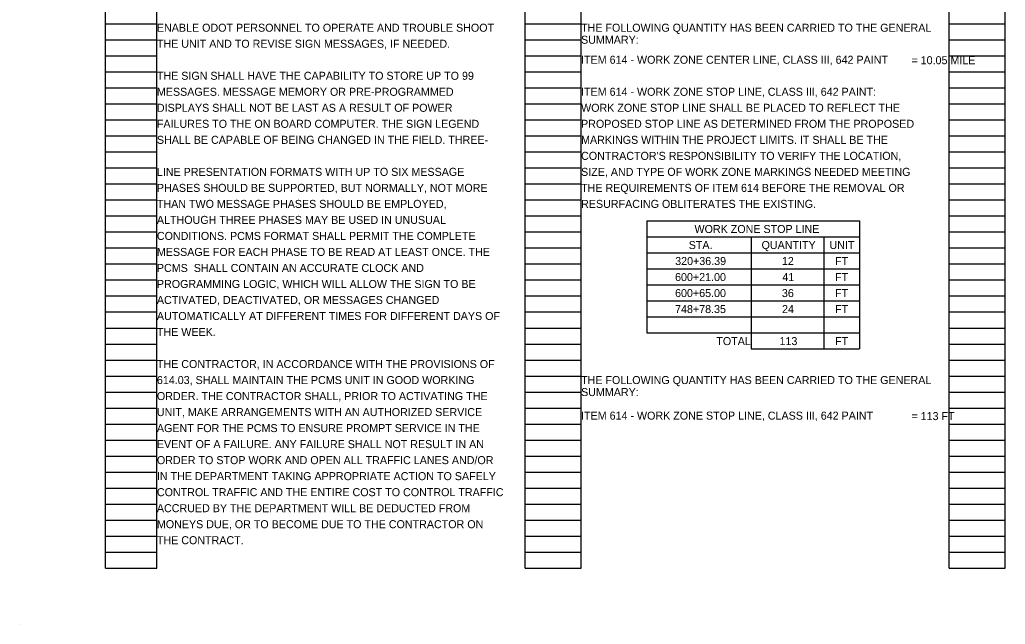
# Model space of a CAD drawing. Extents: x 63 to 145.9, y -75 to 21.1.
# Drawn here: x 62.97 to 80.21, y -50 to -39.43 of the extents above; entities that cross this region are included whole.
import ezdxf

# ---------------------------------------------------------------- set-up
doc = ezdxf.new("R2010")
doc.units = 0
doc.layers.add('AP_P_Airside', color=7, linetype='Continuous')
doc.layers.add('SH_Text', color=7, linetype='Continuous')

msp = doc.modelspace()

# ---------------------------------------------------------------- linework, layer by layer
at = {"layer": 'AP_P_Airside'}
for p, q in [((73.935, -42.945), (77.658, -42.945)), ((73.935, -42.945), (73.935, -44.905)), ((77.658, -42.945), (77.658, -45.185)), ((73.935, -43.225), (77.658, -43.225)), ((75.764, -43.225), (75.764, -45.185)), ((77.032, -43.225), (77.032, -45.185)), ((73.935, -43.505), (77.658, -43.505)), ((73.935, -43.785), (77.658, -43.785)), ((73.935, -44.065), (77.658, -44.065)), ((73.935, -44.345), (77.658, -44.345)), ((73.935, -44.625), (77.658, -44.625)), ((73.935, -44.905), (77.658, -44.905)), ((75.764, -45.185), (77.658, -45.185))]:
    msp.add_line(p, q, dxfattribs=at)
at = {"layer": 'SH_Text'}
for p, q in [((64.466, -49.02), (64.466, -28.86)), ((65.366, -49.02), (65.366, -28.86)), ((71.806, -49.02), (71.806, -28.86)), ((72.786, -49.02), (72.786, -28.86)), ((79.226, -49.02), (79.226, -28.86)), ((80.206, -49.02), (80.206, -28.86)), ((64.466, -39.5), (65.366, -39.5)), ((71.806, -39.5), (72.786, -39.5)), ((79.226, -39.5), (80.206, -39.5)), ((64.466, -39.78), (65.366, -39.78)), ((71.806, -39.78), (72.786, -39.78)), ((79.226, -39.78), (80.206, -39.78)), ((64.466, -40.06), (65.366, -40.06)), ((71.806, -40.06), (72.786, -40.06)), ((79.226, -40.06), (80.206, -40.06)), ((64.466, -40.34), (65.366, -40.34)), ((71.806, -40.34), (72.786, -40.34)), ((79.226, -40.34), (80.206, -40.34)), ((64.466, -40.62), (65.366, -40.62)), ((71.806, -40.62), (72.786, -40.62)), ((79.226, -40.62), (80.206, -40.62)), ((64.466, -40.9), (65.366, -40.9)), ((71.806, -40.9), (72.786, -40.9)), ((79.226, -40.9), (80.206, -40.9)), ((64.466, -41.18), (65.366, -41.18)), ((71.806, -41.18), (72.786, -41.18)), ((79.226, -41.18), (80.206, -41.18)), ((64.466, -41.46), (65.366, -41.46)), ((71.806, -41.46), (72.786, -41.46)), ((79.226, -41.46), (80.206, -41.46)), ((64.466, -41.74), (65.366, -41.74)), ((71.806, -41.74), (72.786, -41.74)), ((79.226, -41.74), (80.206, -41.74)), ((64.466, -42.02), (65.366, -42.02)), ((71.806, -42.02), (72.786, -42.02)), ((79.226, -42.02), (80.206, -42.02)), ((64.466, -42.3), (65.366, -42.3)), ((71.806, -42.3), (72.786, -42.3)), ((79.226, -42.3), (80.206, -42.3)), ((64.466, -42.58), (65.366, -42.58)), ((71.806, -42.58), (72.786, -42.58)), ((79.226, -42.58), (80.206, -42.58)), ((64.466, -42.86), (65.366, -42.86)), ((71.806, -42.86), (72.786, -42.86)), ((79.226, -42.86), (80.206, -42.86)), ((64.466, -43.14), (65.366, -43.14)), ((71.806, -43.14), (72.786, -43.14)), ((79.226, -43.14), (80.206, -43.14)), ((64.466, -43.42), (65.366, -43.42)), ((71.806, -43.42), (72.786, -43.42)), ((79.226, -43.42), (80.206, -43.42)), ((64.466, -43.7), (65.366, -43.7)), ((71.806, -43.7), (72.786, -43.7)), ((79.226, -43.7), (80.206, -43.7)), ((64.466, -43.98), (65.366, -43.98)), ((71.806, -43.98), (72.786, -43.98)), ((79.226, -43.98), (80.206, -43.98)), ((64.466, -44.26), (65.366, -44.26)), ((71.806, -44.26), (72.786, -44.26)), ((79.226, -44.26), (80.206, -44.26)), ((64.466, -44.54), (65.366, -44.54)), ((71.806, -44.54), (72.786, -44.54)), ((79.226, -44.54), (80.206, -44.54)), ((64.466, -44.82), (65.366, -44.82)), ((71.806, -44.82), (72.786, -44.82)), ((79.226, -44.82), (80.206, -44.82)), ((64.466, -45.1), (65.366, -45.1)), ((71.806, -45.1), (72.786, -45.1)), ((79.226, -45.1), (80.206, -45.1)), ((64.466, -45.38), (65.366, -45.38)), ((71.806, -45.38), (72.786, -45.38)), ((79.226, -45.38), (80.206, -45.38)), ((64.466, -45.66), (65.366, -45.66)), ((71.806, -45.66), (72.786, -45.66)), ((79.226, -45.66), (80.206, -45.66)), ((64.466, -45.94), (65.366, -45.94)), ((71.806, -45.94), (72.786, -45.94)), ((79.226, -45.94), (80.206, -45.94)), ((64.466, -46.22), (65.366, -46.22)), ((71.806, -46.22), (72.786, -46.22)), ((79.226, -46.22), (80.206, -46.22)), ((64.466, -46.5), (65.366, -46.5)), ((71.806, -46.5), (72.786, -46.5)), ((79.226, -46.5), (80.206, -46.5)), ((64.466, -46.78), (65.366, -46.78)), ((71.806, -46.78), (72.786, -46.78)), ((79.226, -46.78), (80.206, -46.78)), ((64.466, -47.06), (65.366, -47.06)), ((71.806, -47.06), (72.786, -47.06)), ((79.226, -47.06), (80.206, -47.06)), ((64.466, -47.34), (65.366, -47.34)), ((71.806, -47.34), (72.786, -47.34)), ((79.226, -47.34), (80.206, -47.34)), ((64.466, -47.62), (65.366, -47.62)), ((71.806, -47.62), (72.786, -47.62)), ((79.226, -47.62), (80.206, -47.62)), ((64.466, -47.9), (65.366, -47.9)), ((71.806, -47.9), (72.786, -47.9)), ((79.226, -47.9), (80.206, -47.9)), ((64.466, -48.18), (65.366, -48.18)), ((71.806, -48.18), (72.786, -48.18)), ((79.226, -48.18), (80.206, -48.18)), ((64.466, -48.46), (65.366, -48.46)), ((71.806, -48.46), (72.786, -48.46)), ((79.226, -48.46), (80.206, -48.46)), ((64.466, -48.74), (65.366, -48.74)), ((71.806, -48.74), (72.786, -48.74)), ((79.226, -48.74), (80.206, -48.74)), ((64.466, -49.02), (65.366, -49.02)), ((71.806, -49.02), (72.786, -49.02)), ((79.226, -49.02), (80.206, -49.02)), ((62.966, -50), (62.966, -50))]:
    msp.add_line(p, q, dxfattribs=at)

# ---------------------------------------------------------------- texts
at = {"layer": 'AP_P_Airside'}
for s, p in [('ENABLE ODOT PERSONNEL TO OPERATE AND TROUBLE SHOOT ', (65.366, -39.64)), ('THE FOLLOWING QUANTITY HAS BEEN CARRIED TO THE GENERAL ', (72.786, -39.64)), ('THE UNIT AND TO REVISE SIGN MESSAGES, IF NEEDED.', (65.366, -39.92)), ('SUMMARY:', (72.786, -39.85)), ('ITEM 614 - WORK ZONE CENTER LINE, CLASS III, 642 PAINT', (72.786, -40.2)), ('= 10.05 MILE', (78.565, -40.208)), ('THE SIGN SHALL HAVE THE CAPABILITY TO STORE UP TO 99 ', (65.366, -40.48)), ('MESSAGES. MESSAGE MEMORY OR PRE-PROGRAMMED ', (65.366, -40.76)), ('ITEM 614 - WORK ZONE STOP LINE, CLASS III, 642 PAINT:', (72.786, -40.76)), ('DISPLAYS SHALL NOT BE LAST AS A RESULT OF POWER ', (65.366, -41.04)), ('WORK ZONE STOP LINE SHALL BE PLACED TO REFLECT THE ', (72.786, -41.04)), ('FAILURES TO THE ON BOARD COMPUTER. THE SIGN LEGEND ', (65.366, -41.32)), ('PROPOSED STOP LINE AS DETERMINED FROM THE PROPOSED ', (72.786, -41.32)), ('SHALL BE CAPABLE OF BEING CHANGED IN THE FIELD. THREE-', (65.366, -41.6)), ('MARKINGS WITHIN THE PROJECT LIMITS. IT SHALL BE THE ', (72.786, -41.6)), ("CONTRACTOR'S RESPONSIBILITY TO VERIFY THE LOCATION, ", (72.786, -41.88)), ('LINE PRESENTATION FORMATS WITH UP TO SIX MESSAGE ', (65.366, -42.16)), ('SIZE, AND TYPE OF WORK ZONE MARKINGS NEEDED MEETING ', (72.786, -42.16)), ('PHASES SHOULD BE SUPPORTED, BUT NORMALLY, NOT MORE ', (65.366, -42.44)), ('THE REQUIREMENTS OF ITEM 614 BEFORE THE REMOVAL OR ', (72.786, -42.44)), ('THAN TWO MESSAGE PHASES SHOULD BE EMPLOYED, ', (65.366, -42.72)), ('RESURFACING OBLITERATES THE EXISTING.', (72.786, -42.72)), ('ALTHOUGH THREE PHASES MAY BE USED IN UNUSUAL ', (65.366, -43)), ('WORK ZONE STOP LINE', (74.77, -43.159)), ('CONDITIONS. PCMS FORMAT SHALL PERMIT THE COMPLETE ', (65.366, -43.28)), ('MESSAGE FOR EACH PHASE TO BE READ AT LEAST ONCE. THE ', (65.366, -43.56)), ('STA.', (74.669, -43.439)), ('QUANTITY', (75.943, -43.439)), ('UNIT', (77.131, -43.439)), ('320+36.39', (74.432, -43.719)), ('12', (76.299, -43.719)), ('FT', (77.229, -43.719)), ('PCMS  SHALL CONTAIN AN ACCURATE CLOCK AND ', (65.366, -43.84)), ('600+21.00', (74.43, -43.999)), ('41', (76.307, -43.999)), ('FT', (77.229, -43.999)), ('PROGRAMMING LOGIC, WHICH WILL ALLOW THE SIGN TO BE ', (65.366, -44.12)), ('ACTIVATED, DEACTIVATED, OR MESSAGES CHANGED ', (65.366, -44.4)), ('600+65.00', (74.43, -44.279)), ('36', (76.299, -44.279)), ('FT', (77.229, -44.279)), ('748+78.35', (74.43, -44.559)), ('24', (76.301, -44.559)), ('FT', (77.229, -44.559)), ('AUTOMATICALLY AT DIFFERENT TIMES FOR DIFFERENT DAYS OF ', (65.366, -44.68)), ('THE WEEK.', (65.366, -44.96)), ('TOTAL', (75.152, -45.119)), ('113', (76.257, -45.119)), ('FT', (77.229, -45.119)), ('THE CONTRACTOR, IN ACCORDANCE WITH THE PROVISIONS OF ', (65.366, -45.52)), ('614.03, SHALL MAINTAIN THE PCMS UNIT IN GOOD WORKING ', (65.366, -45.8)), ('THE FOLLOWING QUANTITY HAS BEEN CARRIED TO THE GENERAL ', (72.786, -45.8)), ('ORDER. THE CONTRACTOR SHALL, PRIOR TO ACTIVATING THE ', (65.366, -46.08)), ('SUMMARY:', (72.786, -46.01)), ('UNIT, MAKE ARRANGEMENTS WITH AN AUTHORIZED SERVICE ', (65.366, -46.36)), ('ITEM 614 - WORK ZONE STOP LINE, CLASS III, 642 PAINT', (72.786, -46.422)), ('= 113 FT', (78.565, -46.43)), ('AGENT FOR THE PCMS TO ENSURE PROMPT SERVICE IN THE ', (65.366, -46.64)), ('EVENT OF A FAILURE. ANY FAILURE SHALL NOT RESULT IN AN ', (65.366, -46.92)), ('ORDER TO STOP WORK AND OPEN ALL TRAFFIC LANES AND/OR ', (65.366, -47.2)), ('IN THE DEPARTMENT TAKING APPROPRIATE ACTION TO SAFELY ', (65.366, -47.48)), ('CONTROL TRAFFIC AND THE ENTIRE COST TO CONTROL TRAFFIC ', (65.366, -47.76)), ('ACCRUED BY THE DEPARTMENT WILL BE DEDUCTED FROM ', (65.366, -48.04)), ('MONEYS DUE, OR TO BECOME DUE TO THE CONTRACTOR ON ', (65.366, -48.32)), ('THE CONTRACT.', (65.366, -48.6))]:
    msp.add_text(s, height=0.14, dxfattribs=at).set_placement(p)

doc.saveas('drawing.dxf')
